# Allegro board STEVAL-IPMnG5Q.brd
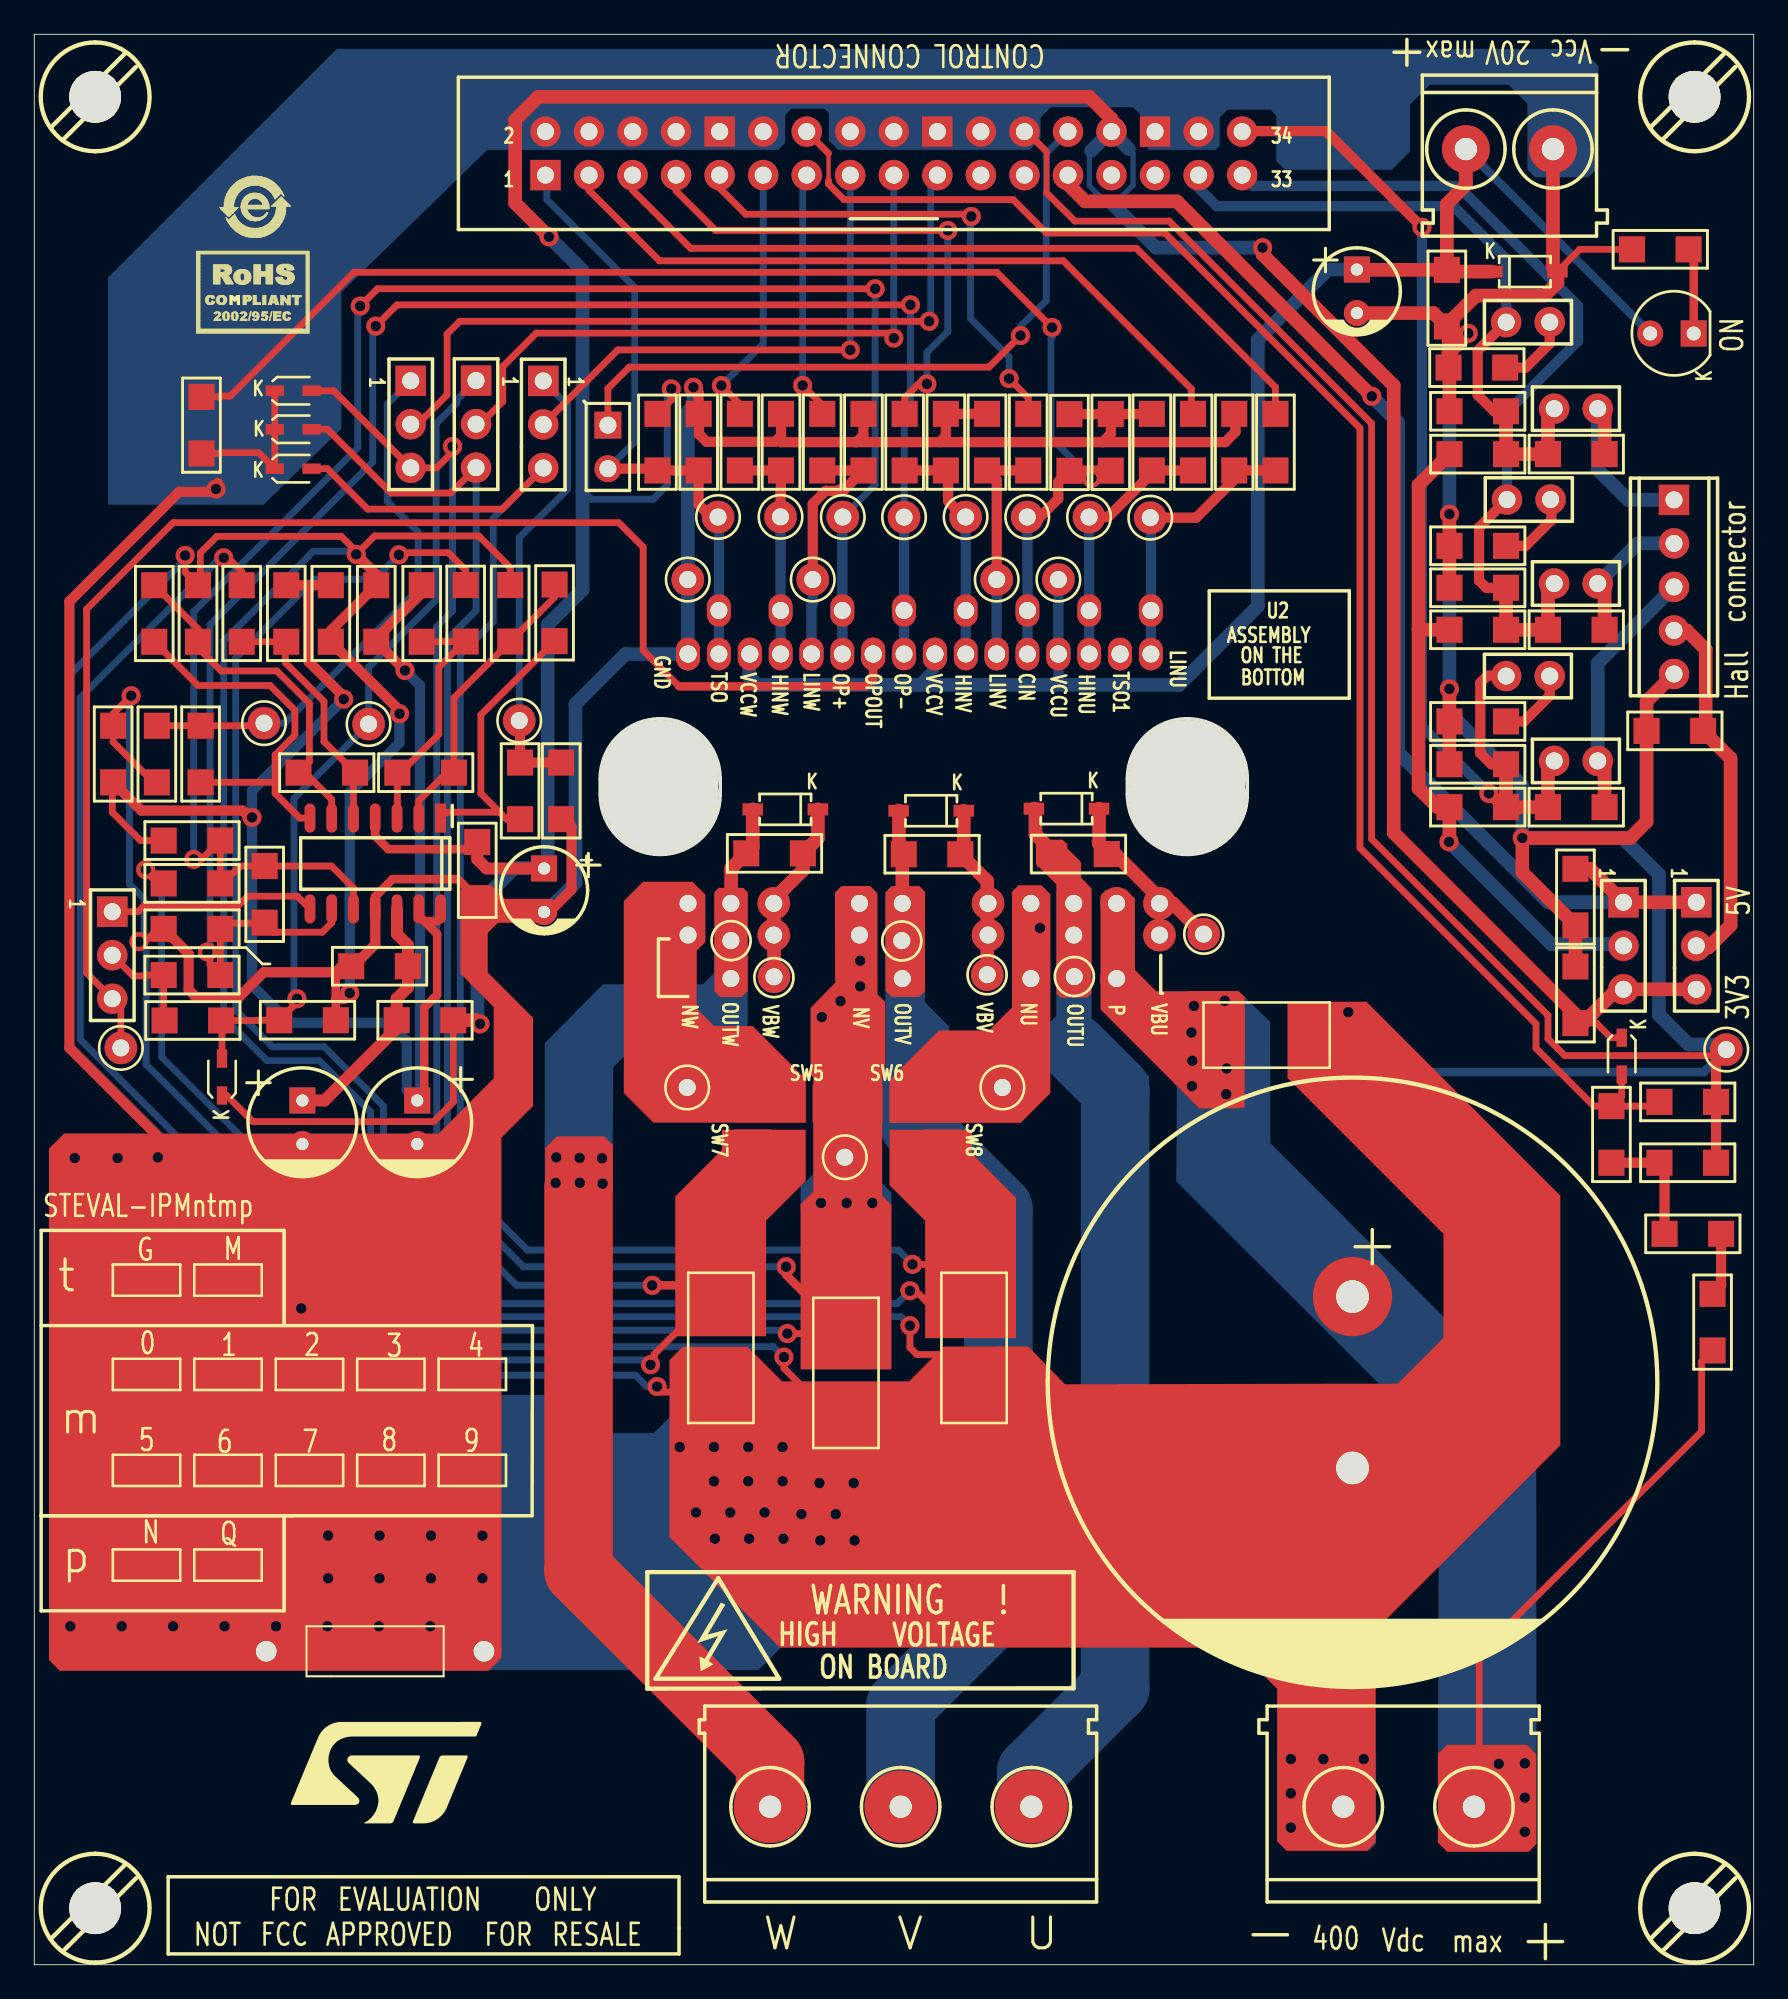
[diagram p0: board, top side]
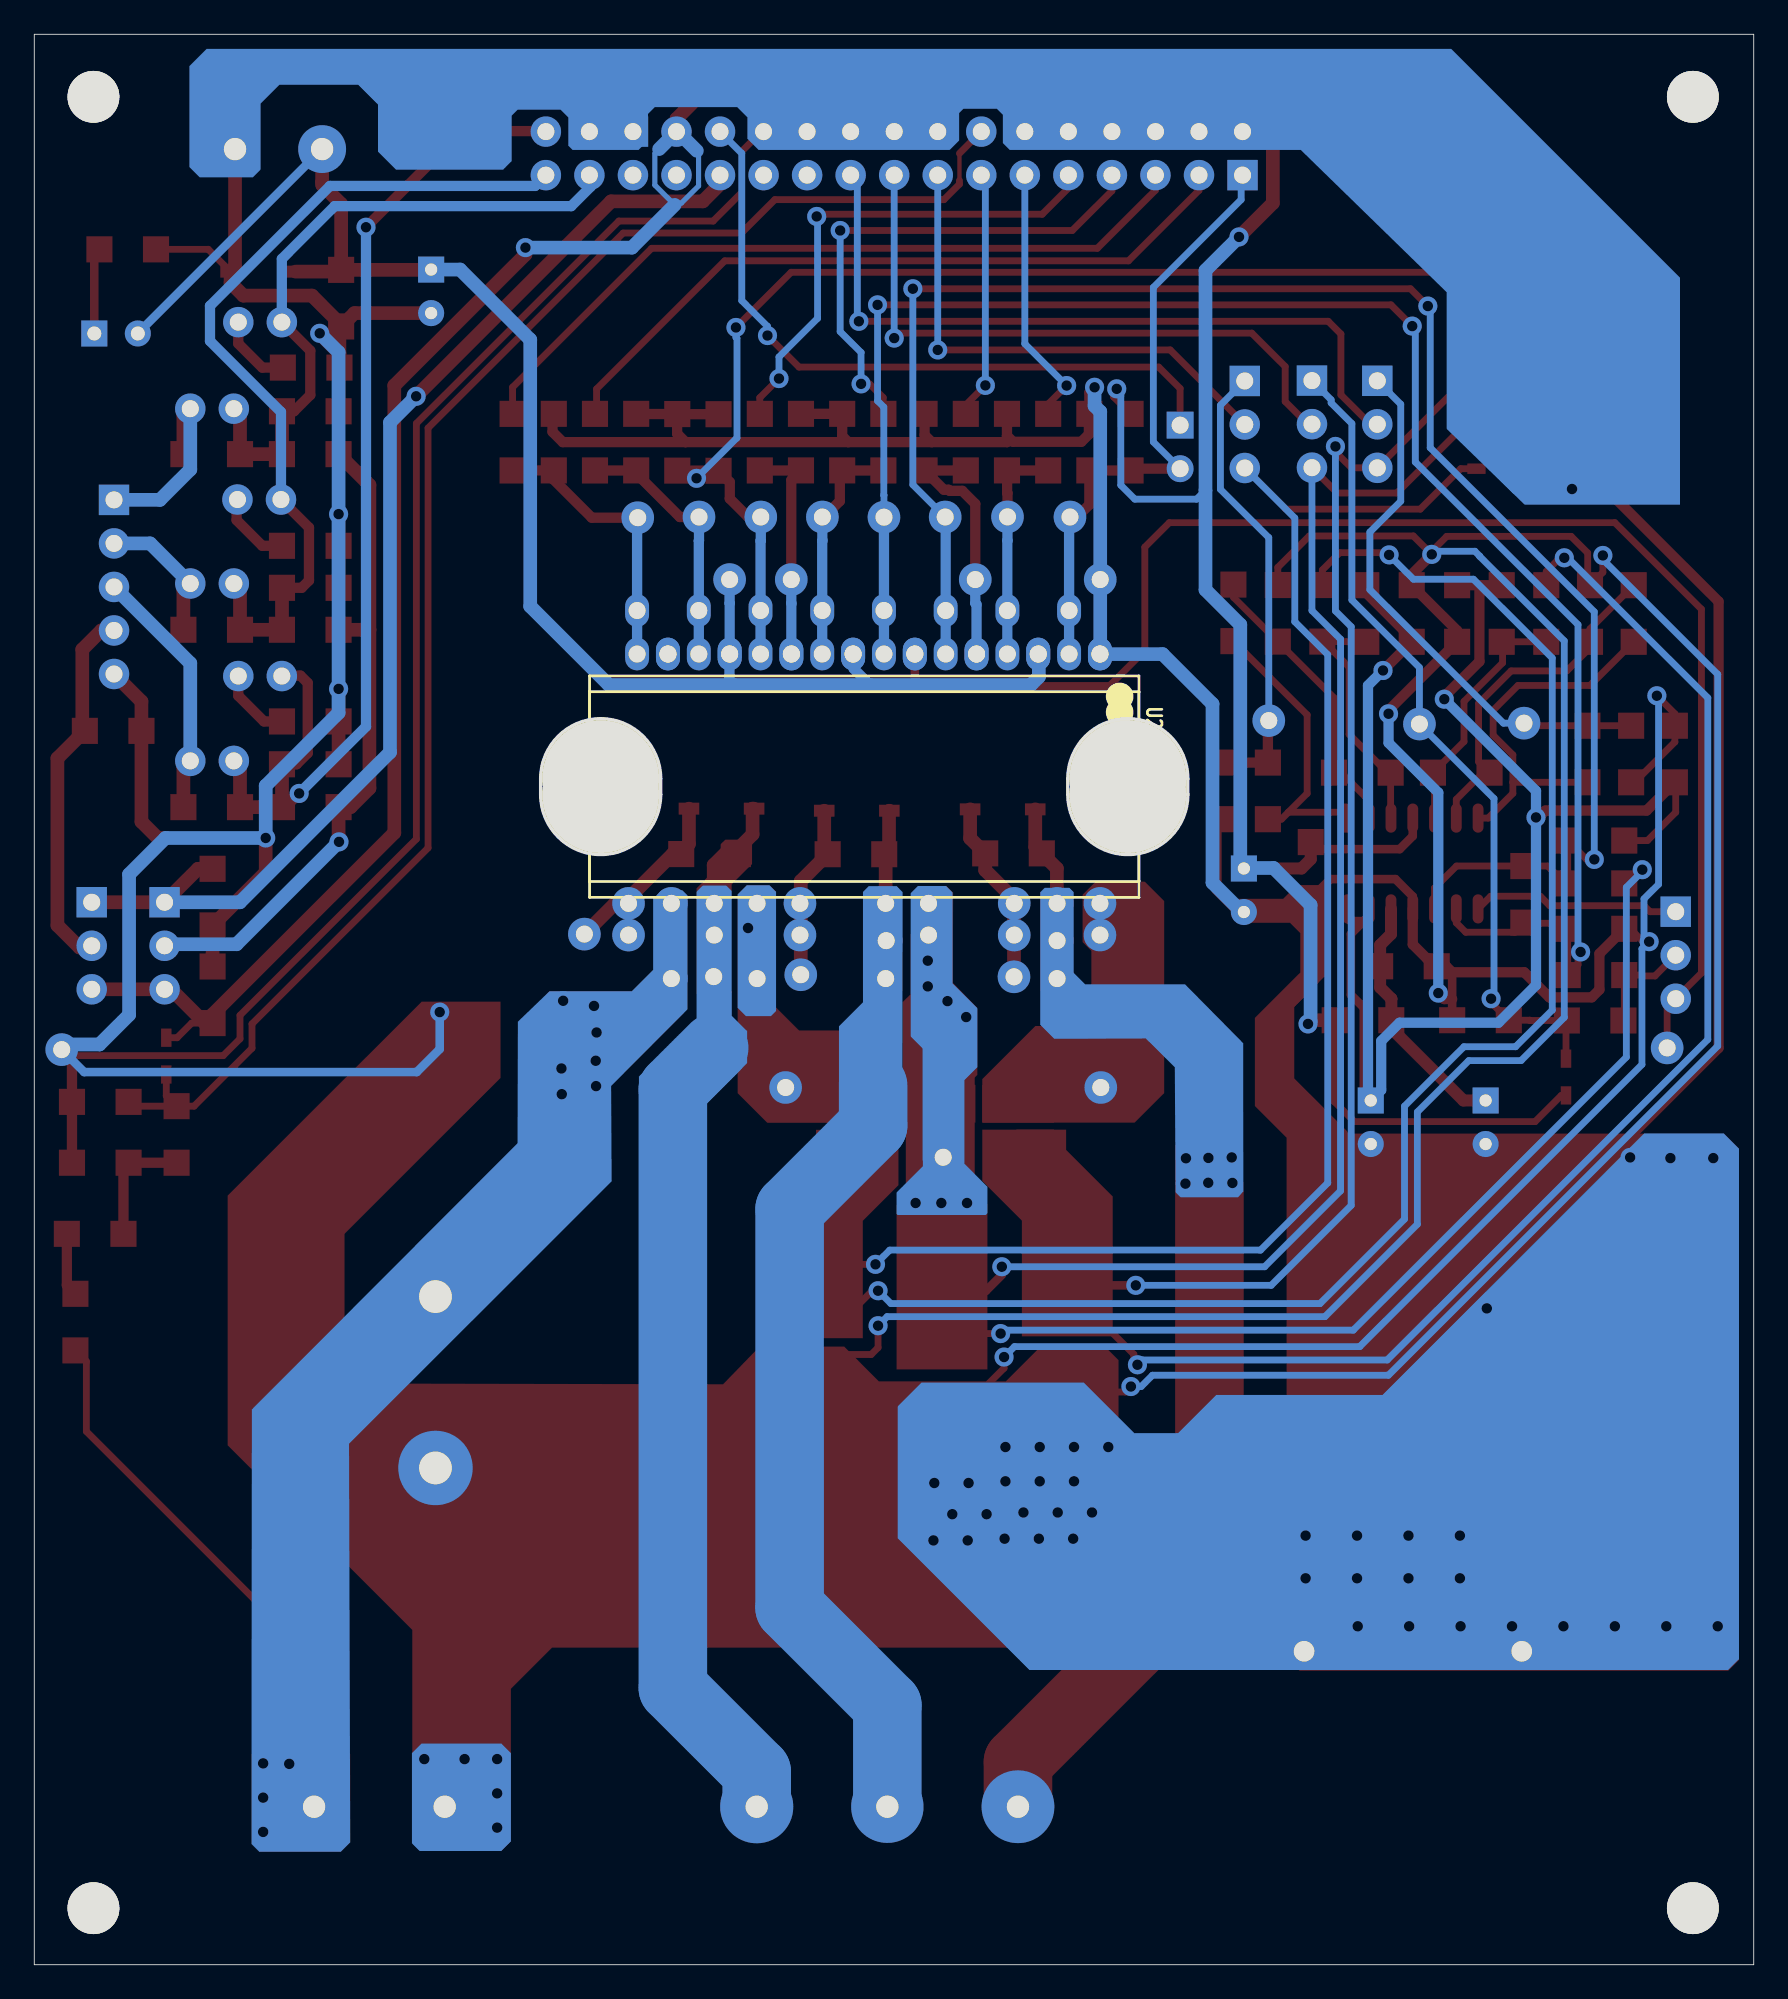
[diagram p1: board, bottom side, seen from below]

Outline 100.3 x 112.65 mm; copper layers: TOP, BOTTOM. Coordinates in mm from the lower left corner of the outline.
Outline path: 0,112.65 100.3,112.65 100.3,0 0,0 0,112.65 ; 33.01,69.21 arc(36.51,72.72) 40.01,69.21 40.01,68.28 arc(36.51,64.78) 33.01,68.28 33.01,69.21 ; 63.76,69.21 arc(67.26,72.72) 70.76,69.21 70.76,68.28 arc(67.26,64.78) 63.76,68.28 63.76,69.21

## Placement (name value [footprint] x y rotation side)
C1  330u/400V  [CPCYL_D1400_LS393_75D]  76.9 33.99 270 top
C2  10n  [SM_C_1206]  96.45 50.35 0 top
C3  47u/35V  [CPCYL_D250_LS100_28D]  15.64 49.16 270 top
C4  47u/35V  [CPCYL_D250_LS100_28D]  22.34 49.16 270 top
C5  2.2u  [SM_R_1206]  60.91 64.81 180 top
C6  2.2u  [SM_R_1206]  52.37 64.8 180 top
C7  2.2u  [SM_R_1206]  43.18 64.85 180 top
C8  1n  [SM_C_1206]  60.39 88.83 90 top
C10  10p  [SM_C_1206]  53.17 88.85 90 top
C11  10p  [SM_C_1206]  48.37 88.85 90 top
C12  10u 50V  [CPCYL_D200_LS100_28D]  77.15 97.65 270 top
C13  100n  [SM_C_1206]  82.4 97.25 90 top
C14  10p  [SM_C_1206]  55.58 88.85 90 top
C15  10p  [SM_C_1206]  70 88.85 90 top
C16  10p  [SM_C_1206]  65.19 88.85 90 top
C17  0,1 uF - 400V  [SMC1812]  69.6 54.25 0 top
C18  3.3n  [SM_C_1206]  38.75 88.85 90 top
C19  10p  [SM_C_1206]  43.56 88.85 90 top
C21  4.7u 50V  [CPCYL_D200_LS100_28D]  29.74 62.7 270 top
C22  10n  [SM_C_1206]  19.95 78.85 90 top
C23  100n  [SM_C_1206]  25.84 63.86 270 top
C24  100p  [SM_C_1206]  22.83 69.56 0 top
C25  330p  [SM_C_1206]  30.74 68.5 270 top
C26  10n  [SM_C_1206]  4.6 70.65 90 top
C27  100p  [SM_C_1206]  13.44 62.46 270 top
C28  10n  [SM_C_1206]  17.3 78.85 270 top
C29  330p  [SM_C_1206]  15.94 55.12 0 top
C30  100p  [SM_C_1206]  17.06 69.56 180 top
C31  330p  [SM_C_1206]  7.15 70.65 270 top
C32  100n  [SM_C_1206]  89.9 56.6 90 top
C33  100n  [SM_C_1206]  89.9 62.3 270 top
C34  100n  [SM_C_1206]  95.7 72 180 top
C35  10p  [SM_C_1206]  84.2 90.65 180 top
C36  10p  [SM_C_1206]  84.2 80.35 180 top
C37  10p  [SM_C_1206]  84.2 70.05 180 top
D1  BAT48JFILM  [SM_SOD-323]  92.6 53.02 270 top
D2  LED Red  [LED3MM]  95.53 95.19 0 top
D3  BAT48JFILM  [SM_SOD-323]  15.1 91.85 0 top
D4  BAT48JFILM  [SM_SOD-323]  15.1 89.6 0 top
D5  BAT48JFILM  [SM_SOD-323]  15.1 87.3 0 top
D6  MMSZ5250B  [SOD123]  43.81 67.42 0 top
D7  MMSZ5250B  [SOD123]  52.32 67.34 0 top
D8  MMSZ5250B  [SOD123]  60.21 67.46 0 top
D9  MMSZ5250B  [SOD123]  86.95 98.8 180 top
D10  BAT48JFILM  [SM_SOD-323]  10.95 51.8 90 top
J1  INPUT-dc  [MOR2_7_62MM]  83.98 9.22 90 top
J2  Control Connector  [CONN_IDC_34_HEADER]  50.14 105.7 0 top
J3  Motor Output  [MOR3_7_62MM]  50.54 9.22 90 top
J4  15V  [MOR2_5_08MM]  86.05 105.95 270 top
J5  Encoder/Hall  [STRIP5_SHROUDED_HEADERS_100M_V]  95.65 80.4 270 top
NOREF  -  []  61.99 87.24 90 top
NOREF#2  -  []  7.55 33.83 90 top
NOREF#3  -  []  52.02 50.13 0 top
NOREF#4  -  []  16 91.12 90 top
NOREF#5  -  []  26.55 33.83 90 top
NOREF#6  -  []  5.55 35.08 0 top
NOREF#7  -  []  21.23 68.76 0 top
NOREF#8  -  []  53.74 24.05 0 top
NOREF#9  -  []  25.04 62.26 90 top
NOREF#10  -  []  79.4 77.1 0 top
NOREF#11  -  []  10.3 35.08 0 top
NOREF#12  -  []  45.31 66.52 90 top
NOREF#13  -  []  23.3 28.23 90 top
NOREF#14  -  []  44.36 87.25 90 top
NOREF#15  -  []  63.14 57.55 90 top
NOREF#16  -  []  82.6 71.75 90 top
NOREF#17  -  []  42.76 90.45 0 top
NOREF#18  -  []  14.4 27.25 0 top
NOREF#19  -  []  35.86 65.89 0 top
NOREF#20  -  []  12.3 28.23 90 top
NOREF#21  -  []  20.75 77.25 90 top
NOREF#22  -  []  49.17 87.25 90 top
NOREF#23  -  []  19.15 80.45 0 top
NOREF#24  -  []  4.9 32.85 0 top
NOREF#25  -  []  82.6 82 90 top
NOREF#26  -  []  36.51 69.21 0 top
NOREF#27  -  []  17.54 54.32 90 top
NOREF#28  -  []  15.46 68.76 90 top
NOREF#29  -  [unnamed#2]  96.85 109 0 top
NOREF#30  -  []  27.1 30.45 0 top
NOREF#31  -  []  35.55 87.25 0 top
NOREF#32  -  []  44.01 51.16 0 top
NOREF#33  -  []  57.18 87.25 0 top
NOREF#34  -  []  5.4 69.05 90 top
NOREF#35  -  []  29.94 66.9 0 top
NOREF#36  -  []  13 102.53 0 top
NOREF#37  -  []  83.51 105.95 0 top
NOREF#38  -  []  8.95 88.24 90 top
NOREF#39  -  []  66.79 87.25 90 top
NOREF#40  -  []  7.6 62.3 0 top
NOREF#41  -  [unnamed#2]  3.55 109 0 top
NOREF#42  -  []  94.1 72.8 0 top
NOREF#43  -  []  50.42 67.34 0 top
NOREF#44  -  []  17.05 33.83 90 top
NOREF#45  -  []  97.1 39.1 0 top
NOREF#46  -  []  7.6 58.55 0 top
NOREF#47  -  []  12.62 97.08 0 top
NOREF#48  -  []  54.78 90.45 0 top
NOREF#49  -  []  64.39 90.45 0 top
NOREF#50  -  []  10.8 59.65 90 top
NOREF#51  -  []  38.14 60.09 0 top
NOREF#52  -  []  91.55 88.95 0 top
NOREF#53  -  []  27.54 66.9 0 top
NOREF#54  -  []  98.05 46 90 top
NOREF#55  -  []  91.55 68.35 0 top
NOREF#56  -  []  18.55 30.23 0 top
NOREF#57  -  []  71.6 87.25 90 top
NOREF#58  -  []  0 112.65 0 top
NOREF#59  -  []  82.6 89.85 90 top
NOREF#60  -  []  44.08 50.99 0 top
NOREF#61  -  []  70.8 87.25 90 top
NOREF#62  -  []  16 86.58 90 top
NOREF#63  -  []  91.88 52.12 90 top
NOREF#64  -  []  6.2 77.25 90 top
NOREF#65  -  []  26.96 77.26 90 top
NOREF#66  -  []  33.46 87.3 90 top
NOREF#67  -  []  56.38 87.25 90 top
NOREF#68  -  []  41.16 47.45 0 top
NOREF#69  -  []  29.94 66.9 90 top
NOREF#70  -  []  8.1 24.92 0 top
NOREF#71  -  []  24.55 35.08 0 top
NOREF#72  -  []  52.55 47.45 90 top
NOREF#73  -  []  21.74 57.47 90 top
NOREF#74  -  []  27.54 66.9 90 top
NOREF#75  -  []  98.05 49.55 90 top
NOREF#76  -  []  79.4 65.15 90 top
NOREF#77  -  []  11.3 77.25 0 top
NOREF#78  -  []  5.55 29.48 0 top
NOREF#79  -  []  13.21 51.2 0 top
NOREF#80  -  []  48.2 50.99 0 top
NOREF#81  -  []  14.34 54.32 0 top
NOREF#82  -  []  6.35 69.05 90 top
NOREF#83  -  []  94.85 49.55 0 top
NOREF#84  -  []  32.25 63.09 0 top
NOREF#85  -  []  22.35 30.45 0 top
NOREF#86  -  []  49.97 87.25 90 top
NOREF#87  -  []  93.25 100.9 0 top
NOREF#88  -  []  65.99 87.25 90 top
NOREF#89  -  []  85.05 98.8 0 top
NOREF#90  -  []  14.2 86.58 0 top
NOREF#91  -  []  22.43 66.91 0 top
NOREF#92  -  []  69.2 90.45 0 top
NOREF#93  -  []  4.9 38.35 0 top
NOREF#94  -  []  9.65 32.85 0 top
NOREF#95  -  []  36.51 68.28 0 top
NOREF#96  -  []  10.23 52.7 0 top
NOREF#97  -  []  8.9 69.05 90 top
NOREF#98  -  []  25.04 62.26 0 top
NOREF#99  -  []  85.45 97.9 90 top
NOREF#100  -  []  66.79 87.25 0 top
NOREF#101  -  []  38.14 61.94 0 top
NOREF#102  -  []  19.15 32.85 0 top
NOREF#103  -  []  100.3 0 90 top
NOREF#104  -  []  79.66 98.04 0 top
NOREF#105  -  []  7.65 54.3 90 top
NOREF#106  -  []  93.25 99.3 90 top
NOREF#107  -  []  91.55 78.7 0 top
NOREF#108  -  []  59.31 65.61 0 top
NOREF#109  -  []  58.31 67.46 0 top
NOREF#110  -  []  21.8 33.83 90 top
NOREF#111  -  []  50.77 64 90 top
NOREF#112  -  []  41.58 64.05 90 top
NOREF#113  -  []  8.95 88.24 0 top
NOREF#114  -  []  12.85 24.92 0 top
NOREF#115  -  []  94.1 71.2 90 top
NOREF#116  -  []  59.31 64.01 90 top
NOREF#117  -  []  7.6 64.8 90 top
NOREF#118  -  []  29.55 77.29 0 top
NOREF#119  -  []  15.64 47.89 90 top
NOREF#120  -  []  5.55 40.58 0 top
NOREF#121  -  []  11.3 77.25 90 top
NOREF#122  -  []  24.74 101.25 90 top
NOREF#123  -  []  7.65 55.9 0 top
NOREF#124  -  []  40.36 87.25 0 top
NOREF#125  -  []  15.5 77.25 90 top
NOREF#126  -  []  82.6 91.45 0 top
NOREF#127  -  []  57.18 87.25 90 top
NOREF#128  -  []  29.82 104.43 0 top
NOREF#129  -  []  24.36 77.26 90 top
NOREF#130  -  []  92.8 46.85 90 top
NOREF#131  -  []  59.59 90.43 0 top
NOREF#132  -  []  79.4 87.35 0 top
NOREF#133  -  []  82.6 83.6 0 top
NOREF#134  -  []  14.2 91.12 0 top
NOREF#135  -  []  4.3 24.7 0 top
NOREF#136  -  []  8.9 69.05 0 top
NOREF#137  -  []  95.15 43.45 0 top
NOREF#138  -  [unnamed#2]  3.55 3.3 0 top
NOREF#139  -  []  24.43 68.76 90 top
NOREF#140  -  []  7.6 59.65 0 top
NOREF#141  -  []  42.75 87.25 90 top
NOREF#142  -  []  94.26 95.19 0 top
NOREF#143  -  []  81.6 98.85 0 top
NOREF#144  -  []  45.16 87.25 0 top
NOREF#145  -  []  95.15 41.85 90 top
NOREF#146  -  []  23.4 77.25 90 top
NOREF#147  -  []  83.2 95.65 90 top
NOREF#148  -  []  9.65 27.25 0 top
NOREF#149  -  []  21.19 54.32 0 top
NOREF#150  -  []  82.6 79.55 90 top
NOREF#151  -  []  19.91 51.2 0 top
NOREF#152  -  []  85.9 63.9 0 top
NOREF#153  -  []  22.34 47.89 90 top
NOREF#154  -  []  41.58 65.65 0 top
NOREF#155  -  []  61.71 66.56 90 top
NOREF#156  -  []  77.15 96.38 90 top
NOREF#157  -  [unnamed#2]  96.85 3.3 0 top
NOREF#158  -  []  49.97 87.25 0 top
NOREF#159  -  []  12.3 33.83 90 top
NOREF#160  -  []  82.55 94 0 top
NOREF#161  -  []  71.6 87.25 0 top
NOREF#162  -  []  29.74 61.43 90 top
NOREF#163  -  []  39.55 87.25 0 top
NOREF#164  -  []  4.3 22.7 90 top
NOREF#165  -  []  23.9 32.85 0 top
NOREF#166  -  []  79.4 75.5 90 top
NOREF#167  -  []  41.91 67.42 0 top
NOREF#168  -  []  6.2 77.25 0 top
NOREF#169  -  []  61.19 87.23 90 top
NOREF#170  -  []  15.05 35.08 0 top
NOREF#171  -  []  87.5 53.4 90 top
NOREF#172  -  []  9.05 22.7 90 top
NOREF#173  -  []  79.4 85.75 90 top
NOREF#174  -  []  85.9 62.3 90 top
NOREF#175  -  []  40.36 87.25 90 top
NOREF#176  -  []  14.4 32.85 0 top
NOREF#177  -  []  94.75 68.35 90 top
NOREF#178  -  []  79.4 66.75 0 top
NOREF#179  -  []  19.8 35.08 0 top
NOREF#180  -  []  13.3 5.1 0 top
NOREF#181  -  []  15.54 62.26 0 top
NOREF#182  -  []  23.3 30.23 0 top
NOREF#183  -  []  10.3 40.58 0 top
NOREF#184  -  []  40.95 50.13 0 top
NOREF#185  -  []  9.65 38.35 0 top
NOREF#186  -  []  26.96 77.26 0 top
NOREF#187  -  []  61.99 87.24 0 top
NOREF#188  -  []  47.57 90.45 0 top
NOREF#189  -  []  25.05 60.76 90 top
NOREF#190  -  []  21.8 80.45 0 top
NOREF#191  -  []  98.7 35.9 90 top
NOREF#192  -  []  24.74 110.15 0 top
NOREF#193  -  []  53.82 66.44 90 top
NOREF#194  -  []  29.55 77.29 90 top
NOREF#195  -  []  53.97 87.25 90 top
NOREF#196  -  []  65.64 61.94 90 top
NOREF#197  -  []  7.55 39.33 90 top
NOREF#198  -  []  16 88.88 90 top
NOREF#199  -  []  15.05 29.48 0 top
NOREF#200  -  []  70.46 104.43 90 top
NOREF#201  -  []  12.64 60.86 90 top
NOREF#202  -  []  91.88 52.12 0 top
NOREF#203  -  []  87.5 55 0 top
NOREF#204  -  []  3.8 72.25 0 top
NOREF#205  -  []  18.55 28.23 90 top
NOREF#206  -  []  82.6 70.85 0 top
NOREF#207  -  []  50.77 65.6 0 top
NOREF#208  -  []  35.55 87.25 90 top
NOREF#209  -  []  12.64 60.86 0 top
NOREF#210  -  []  94.75 88.95 90 top
NOREF#211  -  []  7.55 28.23 90 top
NOREF#212  -  []  7.6 56.95 90 top
NOREF#213  -  []  91.2 50.05 0 top
NOREF#214  -  []  15.46 70.36 0 top
NOREF#215  -  []  16.5 77.25 90 top
NOREF#216  -  []  24.36 77.26 0 top
NOREF#217  -  []  44.08 49.95 90 top
NOREF#218  -  []  6.35 69.05 0 top
NOREF#219  -  []  18.54 57.47 0 top
NOREF#220  -  []  14.2 88.88 0 top
NOREF#221  -  []  52.55 47.45 0 top
NOREF#222  -  []  48.2 49.9 90 top
NOREF#223  -  []  45.16 87.25 90 top
NOREF#224  -  []  4.9 27.25 0 top
NOREF#225  -  []  8.75 77.25 90 top
NOREF#226  -  []  7.6 66.4 0 top
NOREF#227  -  []  12.3 39.33 90 top
NOREF#228  -  []  52.37 90.45 0 top
NOREF#229  -  []  82.55 92.4 90 top
NOREF#230  -  []  10.3 29.48 0 top
NOREF#231  -  []  10.8 62.3 90 top
NOREF#232  -  []  38.14 76.48 0 top
NOREF#233  -  []  48.5 51.16 0 top
NOREF#234  -  []  94.85 46 0 top
NOREF#235  -  []  13.9 80.45 0 top
NOREF#236  -  []  9.05 24.7 0 top
NOREF#237  -  []  82.6 69.25 90 top
NOREF#238  -  []  16.5 77.25 0 top
NOREF#239  -  []  82.6 73.35 0 top
NOREF#240  -  []  94.75 78.7 90 top
NOREF#241  -  []  8.75 77.25 0 top
NOREF#242  -  []  65.64 60.09 90 top
NOREF#243  -  []  17.05 28.23 90 top
NOREF#244  -  []  11.67 50.9 90 top
NOREF#245  -  []  24.39 54.32 90 top
NOREF#246  -  []  35.86 66.81 0 top
NOREF#247  -  []  41.16 47.45 90 top
NOREF#248  -  []  82.6 81.15 0 top
NOREF#249  -  [unnamed#3]  51.89 68.28 0 bottom
R1  470K  [SM_R_1206]  97.9 37.5 90 top
R2  470K  [SM_R_1206]  96.75 42.65 180 top
R3  120R  [SM_R_1206]  92 48.45 90 top
R4  7k5  [SM_R_1206]  96.45 46.8 0 top
R5  1k0  [SM_R_1206]  22.79 55.12 0 top
R6  1k0  [SM_R_1206]  20.14 58.27 0 top
R7  1k0  [SM_R_1206]  41.16 88.85 270 top
R8  1k0  [SM_R_1206]  50.77 88.85 270 top
R9  1k0  [SM_R_1206]  45.96 88.85 270 top
R10  1k0  [SM_R_1206]  36.35 88.85 270 top
R11  4k7  [SM_R_1206]  62.79 88.84 270 top
R12  5k6  [SM_R_1206]  94.85 100.1 180 top
R13  1k0  [SM_R_1206]  72.4 88.85 270 top
R14  1k0  [SM_R_1206]  57.98 88.85 270 top
R15  1k0  [SM_R_1206]  9.75 89.84 270 top
R16  0.2 1W  [SMR2512]  40.05 38.99 270 top
R17  0.2 1W  [SMR2512]  47.35 37.53 270 top
R18  0.2 1W  [SMR2512]  54.82 38.99 270 top
R19  1k0  [SM_R_1206]  67.59 88.85 270 top
R20  1k9  [SM_R_1206]  22.6 78.85 90 top
R21  1k0  [SM_R_1206]  25.16 78.86 270 top
R22  1k  [SM_R_1206]  28.34 68.5 270 top
R23  1k0  [SM_R_1206]  27.76 78.86 270 top
R24  1k9  [SM_R_1206]  30.35 78.89 270 top
R25  1k9  [SM_R_1206]  9.2 65.6 180 top
R26  1k0  [SM_R_1206]  9.2 63.1 0 top
R27  1k0  [SM_R_1206]  9.2 60.45 0 top
R28  1k9  [SM_R_1206]  14.7 78.85 90 top
R29  1k9  [SM_R_1206]  9.2 57.75 180 top
R30  1k0  [SM_R_1206]  12.1 78.85 270 top
R31  1k  [SM_R_1206]  9.7 70.65 270 top
R32  1k0  [SM_R_1206]  9.55 78.85 270 top
R33  1k9  [SM_R_1206]  7 78.85 270 top
R34  4k7  [SM_R_1206]  84.2 88.15 0 top
R35  4k7  [SM_R_1206]  84.2 77.9 0 top
R36  4k7  [SM_R_1206]  84.2 67.55 0 top
R37  2k4  [SM_R_1206]  89.95 88.15 180 top
R38  2k4  [SM_R_1206]  89.95 77.9 180 top
R39  2k4  [SM_R_1206]  89.95 67.55 180 top
R40  4k7  [SM_R_1206]  84.15 93.2 180 top
R41  4k7  [SM_R_1206]  84.2 82.8 180 top
R42  4k7  [SM_R_1206]  84.2 72.55 180 top
R43  1k  [SM_R_1206]  9.25 55.1 180 top
RC1  0  [SM_R_0805]  6.55 39.95 0 top
RC2  0  [SM_R_0805]  11.3 39.95 0 top
RC3  0  [SM_R_0805]  6.55 34.45 0 top
RC4  0  [SM_R_0805]  11.3 34.45 0 top
RC5  0  [SM_R_0805]  16.05 34.45 0 top
RC6  0  [SM_R_0805]  20.8 34.45 0 top
RC7  0  [SM_R_0805]  25.55 34.45 0 top
RC8  0  [SM_R_0805]  6.55 28.85 0 top
RC9  0  [SM_R_0805]  11.3 28.85 0 top
RC10  0  [SM_R_0805]  16.05 28.85 0 top
RC11  0  [SM_R_0805]  20.8 28.85 0 top
RC12  0  [SM_R_0805]  25.55 28.85 0 top
RC13  0  [SM_R_0805]  6.55 23.32 0 top
RC14  0  [SM_R_0805]  11.3 23.32 0 top
SW1  jump3  [STRIP3_100M_V]  29.69 92.42 270 top
SW2  jump3  [STRIP3_100M_V]  25.77 92.44 270 top
SW3  jump3  [STRIP3_100M_V]  21.96 92.43 270 top
SW4  SW SLIDE-SPST_0  [SIPTM2002]  33.46 89.84 270 top
SW5  SW SLIDE-SPST_0  [SM_R_0603]  45.2 50.24 0 top
SW6  SW SLIDE-SPST_0  [SM_R_0603]  49.69 50.24 0 top
SW7  SW SLIDE-SPST_0  [SM_R_0603]  41.91 48.94 90 top
SW8  SW SLIDE-SPST_0  [SM_R_0603]  52.98 48.94 90 top
SW9  jump3  [STRIP3_100M_V]  92.7 62 270 top
SW10  SW SLIDE-SPST_0  [JUMPER100M]  91.2 90.8 180 top
SW11  SW SLIDE-SPST_0  [JUMPER100M]  91.2 80.6 180 top
SW12  SW SLIDE-SPST_0  [JUMPER100M]  91.2 70.25 180 top
SW13  SW SLIDE-SPST_0  [JUMPER100M]  88.4 95.85 180 top
SW14  SW SLIDE-SPST_0  [JUMPER100M]  88.45 85.5 180 top
SW15  SW SLIDE-SPST_0  [JUMPER100M]  88.4 75.2 180 top
SW16  jump3  [STRIP3_100M_V]  96.95 62 270 top
SW17  jump3  [STRIP3_100M_V]  4.55 61.45 270 top
TP1  T POINT F  [TESTPOINT_1MM]  40.64 59.76 0 top
TP2  T POINT F  [TESTPOINT_1MM]  43.53 84.49 0 top
TP3  T POINT F  [TESTPOINT_1MM]  59.74 80.83 0 top
TP4  T POINT F  [TESTPOINT_1MM]  39.89 84.48 0 top
TP5  T POINT F  [TESTPOINT_1MM]  45.41 80.83 0 top
TP6  T POINT F  [TESTPOINT_1MM]  47.16 84.48 0 top
TP7  T POINT F  [TESTPOINT_1MM]  5.05 53.5 0 top
TP8  T POINT F  [TESTPOINT_1MM]  50.74 84.47 0 top
TP9  T POINT F  [TESTPOINT_1MM]  43.15 57.65 0 top
TP10  T POINT F  [TESTPOINT_1MM]  50.61 59.76 0 top
TP11  T POINT F  [TESTPOINT_1MM]  47.28 47.12 0 top
TP12  T POINT F  [TESTPOINT_1MM]  54.33 84.48 0 top
TP13  T POINT F  [TESTPOINT_1MM]  55.59 57.77 0 top
TP14  T POINT F  [TESTPOINT_1MM]  56.14 80.83 0 top
TP15  T POINT F  [TESTPOINT_1MM]  57.92 84.48 0 top
TP16  T POINT F  [TESTPOINT_1MM]  56.47 51.19 0 top
TP17  T POINT F  [TESTPOINT_1MM]  38.09 51.19 0 top
TP18  T POINT F  [TESTPOINT_1MM]  60.67 57.66 0 top
TP19  T POINT F  [TESTPOINT_1MM]  68.21 60.14 0 top
TP20  T POINT F  [TESTPOINT_1MM]  65.1 84.44 0 top
TP21  SW SLIDE-SPST_0  [JUMP1M5PITCH12X7]  19.88 18.29 0 top
TP22  T POINT F  [TESTPOINT_1MM]  38.12 80.83 0 top
TP23  T POINT F  [TESTPOINT_1MM]  61.53 84.48 0 top
TP24  T POINT F  [TESTPOINT_1MM]  28.29 72.6 0 top
TP25  T POINT F  [TESTPOINT_1MM]  19.5 72.4 0 top
TP26  T POINT F  [TESTPOINT_1MM]  13.4 72.45 0 top
TP27  T POINT F  [TESTPOINT_1MM]  98.7 53.4 0 top
U1  TSV994  [SO14]  19.89 64.26 180 top
U2  STGIPQ5C60T-xy  [N2DIP26L]  51.89 69.21 0 bottom

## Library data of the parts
C1 = CAPACITOR POL_2
C2 C8 C10 C11 C13-C16 C18 C19 C22-C37 = CAPACITOR NON-POL
C3 C4 C12 C21 = CAPACITOR POL_1
C5-C7 C17 = C_0
D1 D10 = 1N4148_0
D2 = F5F1_1
D3 = DIODE_1
D4 = DIODE_2
D5 = DIODE_3
D6 = MA745/TO_0
D7 = MA745/TO_1
D8 = MA745/TO_2
D9 = MA745/TO_3
J1 J4 = CON2_0
J2 = CON34A
J3 = CON2_1
J5 = CON2_2
R1-R33 R37-R39 R43 RC1-RC14 = R_0
R34-R36 R40-R42 = R_1
SW1-SW3 SW9 SW16 SW17 = jump3
SW4-SW8 SW10-SW15 = SW SLIDE-SPST_0
TP1-TP20 TP22-TP27 = T POINT F
TP21 = SW SLIDE-SPST_4
U1 = TL084
U2 = 80C552/FP_19

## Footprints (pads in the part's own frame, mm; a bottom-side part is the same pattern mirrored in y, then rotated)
CONN_IDC_34_HEADER
  rect 1.778x1.778 hole 0.991: 1(-20.32,-1.27) 10(-10.16,1.27) 20(2.54,1.27) 30(15.24,1.27)
  round 1.778 hole 0.991: 2(-20.32,1.27) 3(-17.78,-1.27) 4(-17.78,1.27) 5(-15.24,-1.27) 6(-15.24,1.27) 7(-12.7,-1.27) 8(-12.7,1.27) 9(-10.16,-1.27) 11(-7.62,-1.27) 12(-7.62,1.27) 13(-5.08,-1.27) 14(-5.08,1.27) 15(-2.54,-1.27) 16(-2.54,1.27) 17(0,-1.27) 18(0,1.27) 19(2.54,-1.27) 21(5.08,-1.27) 22(5.08,1.27) 23(7.62,-1.27) 24(7.62,1.27) 25(10.16,-1.27) 26(10.16,1.27) 27(12.7,-1.27) 28(12.7,1.27) 29(15.24,-1.27) 31(17.78,-1.27) 32(17.78,1.27) 33(20.32,-1.27) 34(20.32,1.27)
CPCYL_D200_LS100_28D
  rect 1.524x1.524 hole 0.711: 1(-1.27,0)
  round 1.524 hole 0.711: 2(1.27,0)
CPCYL_D250_LS100_28D
  rect 1.524x1.524 hole 0.711: 1(-1.27,0)
  round 1.524 hole 0.711: 2(1.27,0)
CPCYL_D1400_LS393_75D
  rect 2.921x2.921 hole 1.905: 1(-5,0)
  round 2.921 hole 1.905: 2(5,0)
JUMP1M5PITCH12X7
  round 2.032 hole 1.199: 1(-6.35,0) 2(6.35,0)
JUMPER100M
  round 1.778 hole 0.991: 1(0,0) 2(2.54,0)
LED3MM
  round 1.524 hole 0.813: 1(-1.27,0)
  rect 1.524x1.524 hole 0.813: 2(1.27,0)
MOR2_5_08MM
  round 2.794 hole 1.3: 1(0,2.54) 2(0,-2.54)
MOR2_7_62MM
  rect 2.794x2.794 hole 1.3: 1(0,0)
  round 2.794 hole 1.3: 2(0,7.62)
MOR3_7_62MM
  round 2.794 hole 1.3: 1(0,-7.62) 2(0,0) 3(0,7.62)
N2DIP26L
  round 6.8 hole 7 unplated: (-15.375,0) (15.375,0)
  oval 1.397x1.905 hole 0.991: 1(-13.75,-7.275) 2(-11.95,-7.275) 3(-10.15,-7.275) 4(-8.35,-7.275) 5(-6.55,-7.275) 6(-4.75,-7.275) 7(-2.95,-7.275) 8(-1.15,-7.275) 9(0.65,-7.275) 10(2.45,-7.275) 11(4.25,-7.275) 12(6.05,-7.275) 13(7.85,-7.275) 14(9.65,-7.275) 15(11.45,-7.275) 16(13.25,-7.275)
  round 1.905 hole 0.991: 17(13.75,7.275) 18(11.25,7.275) 19(8.75,7.275) 20(6.25,7.275) 21(3.75,7.275) 22(-1.25,7.275) 23(-3.75,7.275) 24(-8.75,7.275) 25(-11.25,7.275) 26(-13.75,7.275)
SIPTM2002
  rect 1.575x1.575 hole 0.991: 1(0,0)
  round 1.575 hole 0.991: 2(2.54,0)
SM_C_1206
  rect 1.524x1.524 smd: 1(-1.651,0) 2(1.651,0)
SM_R_0603
  rect 2x2.2 smd: 1(-1.2,0) 2(1.2,0)
SM_R_0805
  rect 1.194x1.194 smd: 1(1.053,0) 2(-1.053,0)
SM_R_1206
  rect 1.524x1.524 smd: 1(-1.651,0) 2(1.651,0)
SM_SOD-323
  rect 1.067x0.61 smd: 1(1.073,0) 2(-1.073,0)
SMC1812
  rect 2.032x3.048 smd: 1(0,0) 2(4.572,0)
SMR2512
  rect 1.93x3.048 smd: 1(0,0) 2(5.994,0)
SO14
  rect 0.635x1.702 smd: 1(-3.81,-2.649)
  oval 0.635x1.702 smd: 2(-2.54,-2.649) 3(-1.27,-2.649) 4(0,-2.649) 5(1.27,-2.649) 6(2.54,-2.649) 7(3.81,-2.649) 8(3.81,2.649) 9(2.54,2.649) 10(1.27,2.649) 11(0,2.649) 12(-1.27,2.649) 13(-2.54,2.649) 14(-3.81,2.649)
SOD123
  rect 1.2x0.7 smd: 1(-1.9,0) 2(1.9,0)
STRIP3_100M_V
  rect 1.778x1.778 hole 0.991: 1(0,0)
  round 1.778 hole 0.991: 2(2.54,0) 3(5.08,0)
STRIP5_SHROUDED_HEADERS_100M_V
  rect 1.778x1.778 hole 0.991: 1(-5.08,0)
  round 1.778 hole 0.991: 2(-2.54,0) 3(0,0) 4(2.54,0) 5(5.08,0)
TESTPOINT_1MM
  round 1.905 hole 0.991: 1(0,0)
unnamed#2
  round 3.023 hole 3.2 unplated: (0,0)
unnamed#3
  round 6.8 hole 7 unplated: (-15.375,0) (15.375,0)
  oval 1.397x1.905 hole 0.991: 1(-13.75,-8.2) 2(-11.95,-10.74) 3(-10.15,-8.2) 4(-8.35,-10.74) 5(-6.55,-8.2) 6(-4.75,-10.74) 7(-2.95,-8.2) 8(-1.15,-10.74) 9(0.65,-8.2) 10(2.45,-10.74) 11(4.25,-8.2) 12(6.05,-10.74) 13(7.85,-8.2) 14(9.65,-10.74) 15(11.45,-8.2) 16(13.25,-10.74)
  round 1.905 hole 0.991: 17(13.75,8.2) 18(11.25,10.74) 19(8.75,8.2) 20(6.25,10.74) 21(3.75,8.2) 22(-1.25,10.74) 23(-3.75,8.2) 24(-8.75,8.2) 25(-11.25,10.74) 26(-13.75,8.2)

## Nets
1.65V: C4.1(P) C22.1 C26.1 C28.1 R20.2 R25.2 R28.2 U1.13(IN-) U1.14(OUT)
3.3V: C21.1(P) C23.1 C32.1 D1.2(CATHODE) D10.2(CATHODE) J2.28 R5.2 R10.1 SW9.3 SW16.3 U1.4(V+)
+5V: C33.1 J2.25 SW9.1 SW16.1
GND_SIGNAL: C1.2(N) C2.2 C3.2(N) C4.2(N) C8.2 C10.2 C11.2 C12.2(N) C13.1 C14.2 C15.2 C16.2 C17.2 C18.2 C19.2 C21.2(N) C22.2 C23.2 C25.2 C26.2 C28.2 C29.2 C31.2 C32.2 C33.2 C34.2 C35.2 C36.2 C37.2 D9.1(ANODE) J1.2 J2.2 J2.4 J2.6 J2.8 J2.10 J2.12 J2.16 J2.18 J2.20 J2.22 J2.24 J2.30 J2.32 J4.1 J5.5 R4.2 R6.1 R11.1 R12.2 R16.2 R17.2 R18.2 R23.1 R27.1 R32.1 R40.2 R41.2 R42.2 RC1.1 RC1.2 RC2.1 RC2.2 RC3.1 RC3.2 RC4.1 RC4.2 RC5.1 RC5.2 RC6.1 RC6.2 RC7.1 RC7.2 RC8.1 RC8.2 RC9.1 RC9.2 RC10.1 RC10.2 RC11.1 RC11.2 RC12.1 RC12.2 RC13.1 RC13.2 RC14.1 RC14.2 TP21.1 TP21.2(NO) TP22.1(TP) TP27.1(TP) U1.11(V-) U2.1(GND)
+BUS: C1.1(P) C17.1 J1.1 R1.1 U2.18(P)
BUS_VOLTAGE: C2.1 D1.1(ANODE) J2.14 R3.2
CURRENT_A: J2.15 SW1.2
CURRENT_A_AMP: C25.1 R22.1 SW1.1 TP24.1(TP)
CURRENT_B: J2.17 SW2.2
CURRENT_B_AMP: C29.1 D10.1(ANODE) R43.1 SW2.1 TP25.1(TP)
CURRENT_C: J2.19 SW3.2
CURRENT_C_AMP: C31.1 R31.1 SW3.1 TP26.1(TP)
E1: D5.1(A) R18.1 R21.1 SW1.3 SW8.1
E2: D4.1(A) R17.1 R26.1 SW2.3 SW5.2(NO) SW6.1 TP11.1(TP) U2.23(NV)
E3: D3.1(A) R16.1 R30.1 SW3.3 SW7.1
EM_STOP: C18.1 J2.1 R10.2 SW4.2(NO) TP4.1(TP) U2.2(T/S\D\/OD)
M_PHASE_A: C35.1 J2.31 R34.2 R37.2 SW10.2(NO) SW13.2(NO)
M_PHASE_B: C36.1 J2.33 R35.2 R38.2 SW11.2(NO) SW14.2(NO)
M_PHASE_C: C37.1 J2.34 R36.2 R39.2 SW12.2(NO) SW15.2(NO)
NANO OP+: C27.1 R25.1 R26.2 TP6.1(TP) U1.10(IN+) U2.6(OP+)
NANO OP-: C27.2 R27.2 R29.1 TP8.1(TP) U1.9(IN-) U2.8(OP-)
NANO OPOUT: SW17.3 TP7.1(TP) U2.7(OPOUT)
NTC: J2.26 SW4.1
NTC_BYPASS_RELAY: J2.21
PHASE_A: C5.2 D8.1(ANODE) J3.1 TP18.1(TP) U2.19(U,OUTU)
PHASE_B: C6.2 D7.1(ANODE) J3.2 TP10.1(TP) U2.22(V,OUTV)
PHASE_C: C7.2 D6.1(ANODE) J3.3 TP1.1(TP) U2.25(W, OUTW)
PWM-A-H: J2.3 R19.1
PWM-A-L: J2.5 R13.1
PWM-B-H: J2.7 R8.1
PWM-B-L: J2.9 R14.1
PWM-C-H: J2.11 R7.1
PWM-C-L: J2.13 R9.1
PWM_VREF: J2.29
N6680355: R1.2 R2.1
N6680429: R2.2 R3.1 R4.1
N7418873: C19.1 R7.2 TP2.1(TP) U2.4(HINW)
N7419173: C11.1 R9.2 TP5.1(TP) U2.5(LINW)
N7419575: C15.1 R13.2 TP20.1(TP) U2.16(LINU)
N7419579: C16.1 R19.2 TP23.1(TP) U2.14(HINU)
N7419959: C14.1 R14.2 TP14.1(TP) U2.11(LINV)
N7419967: C10.1 R8.2 TP12.1(TP) U2.10(HINV)
N8602926: C24.1 R20.1 R21.2 U1.3(IN+)
N8603142: C24.2 R23.2 R24.1 U1.2(IN-)
N8608659: R22.2 R24.2 U1.1(OUT)
N8611164: C3.1(P) R5.1 R6.2 U1.12(IN+)
N8745560: D3.2(K) D4.2(K) D5.2(K) R15.2
N8758281: R29.2 R43.2 SW17.2
N8759020: R31.2 R33.2 U1.7(OUT)
N8759128: C30.1 R28.1 R30.2 U1.5(IN+)
N8759136: C30.2 R32.2 R33.1 U1.6(IN-)
N8769015: C34.1 J5.4 SW16.2
N8769177: R34.1 R35.1 R36.1 SW9.2
N8769259: J5.1 R37.1 SW10.1
N8769267: J5.2 R38.1 SW11.1
N8783110: J5.3 R39.1 SW12.1
N8796833: SW6.2(NO) SW8.2(NO) TP16.1(TP) U2.20(NU)
N8856248: C7.1 D6.2(CATHODE) TP9.1(TP) U2.24(VBOOTW)
N8857786: SW5.1 SW7.2(NO) TP17.1(TP) U2.26(NW)
N8867925: C8.1 R11.2 R15.1 TP15.1(TP) U2.12(CIN)
N8869100: C6.1 D7.2(CATHODE) TP13.1(TP) U2.21(VBOOTV)
N8869824: C5.1 D8.2(CATHODE) TP19.1(TP) U2.17(VBOOTU)
N8877212: C12.1(P) C13.2 D2.1(A) D9.2(CATHODE) J4.2 TP3.1(TP) U2.3(VCCW) U2.9(VCCV) U2.13(VCCU)
N8885403: SW17.1 U1.8(OUT)
N8906266: R42.1 SW15.1
N8906381: R41.1 SW14.1
N8906601: R40.1 SW13.1
N88772240: D2.2(C) R12.1

Pads without a net: J2 23 27; NOREF#249 1 2 3 4 5 6 7 8 9 10 11 12 13 14 15 16 17 18 19 20 21 22 23 24 25 26; U2 15

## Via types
v1: diameter 1.118, hole 0.61, TOP to BOTTOM, 125 vias

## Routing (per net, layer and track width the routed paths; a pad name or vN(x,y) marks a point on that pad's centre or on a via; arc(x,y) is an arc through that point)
1.65V: length 103.5
  TOP w0.4: C26.1 4.55,68.95 4.55,67.25 6.2,65.6 R25.2
  TOP w0.5: 22.75,60.9 23.5,60.15 23.5,56.6 22.75,55.85 22.75,50.84 C4.1 ; 22.75,60.9 23.52,60.9 23.7,61.08 U1.14 ; 22.75,60.9 22.43,61.22 U1.13
  TOP w0.6: v1(12.7,66.95) 12.55,66.95 12.15,67.35 6.25,67.35 C26.1 ; R28.2 16,80.5 ; 16,80.5 16,76.05 18.05,74 v1(18.05,73.85) ; 16,80.5 C28.1 ; R20.2 22.6,80.05 19.95,77.4 19.95,77.2 v1(21.62,75.52)
  BOTTOM w0.6: v1(21.62,75.52) 22.5,74.65 22.5,50.59 C4.1 21.73,51.04 21.73,53.9 20.66,54.97 14.89,54.97 12.7,57.16 v1(12.7,66.95) 12.7,68.5 v1(18.05,73.85)
3.3V: length 226.9
  TOP w0.4: D10.2 11.22,50.73 12.75,49.2 23.3,49.2 24.45,50.35 24.45,55.11 R5.2 ; D1.2 91.97,54.1 91.11,54.95 90.35,54.95 ; R10.1 37.34,91.49 37.34,91.96 v1(37.16,91.96)
  TOP w0.5: 25.84,65.51 25.43,65.1 20.65,65.1 19.89,65.86 U1.4
  TOP w0.7: C21.1 26.38,63.97 25.84,64.51 25.84,65.51
  TOP w0.8: v1(30.02,100.83) 28.05,102.8 28.05,107.65 29.4,109 61.55,109 62.84,107.71 62.84,106.97 ; R5.2 25.78,55.12 v1(26,54.9) ; SW16.3 SW9.3 92.6,56.82 92.22,56.82 90.35,54.95 C32.1 89.9,55.45 79.3,66.05 79.3,92.15 71.65,99.8 v1(71.65,100.2)
  BOTTOM w0.28: 64.1,105.7 63.85,105.95
  BOTTOM w0.3: 62.6,102.8 62.55,102.8 61.55,103.8 61.55,105.68 62.84,106.97
  BOTTOM w0.305: 62.94,102.69 64.1,103.85 64.1,105.7
  BOTTOM w0.4: v1(37.16,91.96) 37.33,91.96 36.92,91.55 36.92,86.34 36.1,85.52 32.5,85.52 31.98,86.04
  BOTTOM w0.8: 29.77,64 28,64 25.85,61.85 25.85,55.05 v1(26,54.9) ; 29.77,64 29.95,64.18 29.95,78.2 31.98,80.23 31.98,98.87 v1(30.02,100.83) ; 29.77,64 C21.1 ; 63.85,105.95 62.84,106.96 62.84,106.97 62.77,106.97 61.65,105.85 ; 62.94,102.69 65.44,100.2 v1(71.65,100.2)
+5V: length 69.4
  TOP w0.8: 60.3,104.43 60.3,103.9 61.3,102.9 66.65,102.9 v1(78.03,91.53) ; SW16.1 SW9.1 90.75,63.95 C33.1
  BOTTOM w0.8: SW9.1 88.3,62 79.55,70.75 79.55,90 v1(78.03,91.53)
GND_SIGNAL: length 776.9
  TOP w0.305: 59.05,103.4 59.05,105.8
  TOP w0.4: R12.2 90.15,100.1 D9.1 ; 59.05,103.4 60.7,101.75 66.2,101.75 78.01,89.94 78.01,65.69 88.3,55.4 88.3,54.03 89.28,53.05 97.85,53.05 98.1,52.8 ; 57.76,106.97 57.88,106.97 59.05,105.8 ; 40.1,33.82 39.7,33.42 36.65,33.42 v1(36.33,33.74) ; C31.2 6.95,69 4.6,71.35 C26.2 4.6,73 v1(5.65,74.05) ; v1(8.8,82.24) 8.8,81.25 R32.1 9.69,80.64 9.69,82.39 10.65,83.35 17.91,83.35 18.78,82.48 v1(18.78,82.3) 19.85,83.38 25.92,83.38 27.76,81.54 R23.1 ; R27.1 7.5,60.4 7.15,60.4 6.45,59.7 v1(6.1,59.7) ; 46.52,31.47 46.52,32.02 43.73,34.81 v1(43.73,35.46) ; v1(51.08,37.29) 51.08,36.01 51.48,35.61 53.32,35.61
  TOP w0.5: C29.2 17.59,57.92 ; C23.2 24.7,63.35 20.9,63.35 19.89,62.34 U1.11
  TOP w0.6: 47.95,88.85 43.56,88.85 43.56,89.22 ; 47.95,88.85 48.37,89.27 C11.2 ; 47.95,88.85 52.82,88.85 ; R27.1 9,59 9,56.9 9.45,56.45 11.92,56.45 13.38,57.92 17.59,57.92 17.94,58.27 R6.1 18.92,58.7 19.05,58.7 19.89,59.54 U1.11 ; v1(10.6,86.11) 10.71,86.23 10.71,86.46 10.2,85.95 8.45,85.95 2.05,79.55 2.05,53.5 7.1,48.45 7.1,47.75 15.5,47.75 C3.2 ; 52.82,88.85 62.31,88.85 ; 52.82,88.85 53.17,89.2 C10.2 C14.2 ; 62.31,88.85 62.8,89.34 62.8,90.48 R11.1 ; 62.31,88.85 69.47,88.85 70.07,89.45 70.07,90.43 C15.2 ; R11.1 65.18,90.49 C16.2 ; R11.1 62.78,90.48 C8.2 ; 43.56,89.22 C19.2 ; 43.56,89.22 43.21,88.87 39.22,88.87 38.78,89.31 38.78,90.47 C18.2 38.75,91.75 v1(38.45,92.05) ; v1(18.4,56.7) 18.05,56.35 17.59,56.35 ; 98.1,46.8 98.1,52.8 TP27.1 ; v1(18.78,82.3) 20.1,80.98 20.1,80.65 C22.2 17.3,77.85 17.3,77.2 21.5,73 v1(21.3,73) ; C21.2 29.76,61.45 30.05,61.45 31.34,62.74 31.34,66.41 30.9,66.85 C25.2
  TOP w0.8: v1(14.1,19.75) 14.89,18.96 14.22,18.29 TP21.1 ; v1(82.55,84.65) R41.2 C36.2 ; C23.2 25.84,61.07 26.2,61.43 C21.2 ; J5.5 94.05,73.72 C34.2 94.05,66.7 93.1,65.75 v1(86.8,65.75) 86.8,63.75 C33.2 C32.2 ; 26.1,19.5 26.23,19.37 TP21.2 ; C17.2 75.31,54.25 v1(76.65,55.59) ; C35.2 82.55,93.15 R40.2 82.5,94.03 ; v1(82.55,74.45) R42.2 82.55,70.05 ; 82.5,94.03 82.5,95.5 C13.1 ; 82.5,94.03 83.65,95.18 v1(83.65,95.2) ; C4.2 22.48,47.75 24.05,47.75 27.62,51.32 27.62,55.78 ; C13.1 81.62,96.38 C12.2 ; C13.1 82.4,95.7 84.1,97.4 88.1,97.4 88.85,98.15 D9.1 88.59,99.06 J4.1
  TOP w1: 25.84,61.07 25.84,57.56 27.62,55.78
  BOTTOM w0.4: v1(8.8,82.24) 8.8,82 2.1,75.3 2.1,53.61 21.31,34.4 35.07,34.4 35.73,33.74 v1(36.33,33.74) ; v1(51.08,37.29) 50.55,37.82 25.01,37.82 19.62,43.21 19.62,49.76 16.62,52.76 13.57,52.76 11.05,55.28 11.05,77.25 15.98,82.18 15.98,82.2 16.26,82.48 18.6,82.48 v1(18.78,82.3) ; v1(5.65,74.05) 5.55,73.95 5.55,63.05 6.4,62.2 6.4,60 v1(6.1,59.7) 6.52,59.28 6.52,52.53 22.98,36.07 43.12,36.07 v1(43.73,35.46)
  BOTTOM w0.5: v1(76.65,55.59) 76.65,53.43 77.99,52.09 97.39,52.09 TP27.1
  BOTTOM w0.6: v1(18.4,56.7) 18.4,68.4 21.3,71.3 21.3,72.8 21.5,73 v1(21.3,73) ; J2.2 28.44,108.35 22.3,108.35 17.55,103.6 17.55,89.8 13.86,86.11 v1(10.6,86.11)
  BOTTOM w0.8: C21.2 29.86,61.43 31.57,63.14 31.57,73.57 34.48,76.48 38.13,76.48 U2.1 38.12,76.5 TP22.1 38.12,90.63 38.45,90.96 v1(38.45,92.05) ; TP27.1 98.4,53.7 96.5,53.7 94.77,55.43 94.77,63.63 92.65,65.75 v1(86.8,65.75) 86.8,68.8 82.55,73.05 v1(82.55,74.45) v1(82.55,84.65) 82.55,94.1 v1(83.65,95.2)
  vias: v1(2.1,19.75) v1(2.36,47.07) v1(4.86,47.07) v1(5.1,19.75) v1(7.21,47.11) v1(8.1,19.75) v1(11.1,19.75) v1(15.57,38.3) v1(17.14,25.04) v1(17.14,22.55) v1(17.1,19.75) v1(20.14,25.04) v1(20.14,22.55) v1(20.1,19.75) v1(23.14,25.04) v1(23.14,22.55) v1(23.1,19.75) v1(26.14,25.04) v1(26.14,22.55) v1(37.65,30.21) v1(38.6,26.39) v1(39.65,30.21) v1(39.65,28.21) v1(39.7,24.86) v1(40.6,26.39) v1(41.65,30.21) v1(41.65,28.21) v1(41.7,24.86) v1(42.6,26.39) v1(43.65,30.21) v1(43.65,28.21) v1(43.7,24.86) v1(44.75,26.29) v1(45.8,28.11) v1(45.85,24.76) v1(46.75,26.29) v1(47.8,28.11) v1(47.85,24.76) v1(73.3,12) v1(73.3,10) v1(73.3,8) v1(75.2,12) v1(77.55,12)
+BUS: length 34.5
  TOP w0.305: 84.28,9.52 J1.1
  TOP w0.4: R1.1 97.26,35.21 97.26,31.12 84.28,18.14 84.28,9.52
  TOP w0.6: 69.6,56.2 C17.1
  BOTTOM w3: 76.98,38.91 C1.1
  vias: v1(67.5,54.4) v1(67.55,52.75) v1(67.53,51.27) v1(67.65,55.95) v1(69.45,56.25) v1(69.53,50.8) v1(69.55,52.3) v1(85.43,11.72) v1(86.95,11.75) v1(86.95,9.75) v1(86.95,7.75)
BUS_VOLTAGE: length 91.7
  TOP w0.254: 46.33,104.12 46.33,105.7
  TOP w0.4: R3.2 92.6,50.7 D1.1 ; R3.2 90.98,50.1 87.6,53.48 87.6,54.9 77.33,65.17 77.33,89.67 65.95,101.05 59.05,101.05 57.1,103 47.24,103 46.33,103.91 46.33,104.12 ; R3.2 94.55,50.1 C2.1 ; 45.06,106.97 45.06,106.97 46.33,105.7
CURRENT_A: length 29.9
  TOP w0.4: SW1.2 34.04,94.23 v1(47.6,94.23)
  BOTTOM w0.4: v1(47.6,94.23) J2.15
CURRENT_A_AMP: length 26.4
  TOP w0.6: TP24.1 28.34,72.55 R22.1 C25.1
  BOTTOM w0.4: TP24.1 28.29,83.28 31.11,86.1 31.11,91 SW1.1
CURRENT_B: length 37.5
  TOP w0.4: SW2.2 25.81,89.94 26.05,89.94 27.33,91.22 27.33,93.26 29.28,95.21 49.97,95.21 50.14,95.04 v1(50.14,94.92)
  BOTTOM w0.4: v1(50.14,94.92) J2.17
CURRENT_B_AMP: length 47.9
  TOP w0.4: D10.1 10.95,55.05 R43.1 13.05,55.1 13.07,55.12 C29.1 15.32,56.15 v1(15.32,56.37)
  BOTTOM w0.4: v1(15.32,56.37) 15.15,56.54 15.15,68.05 TP25.1 19.5,75.7 23.44,79.64 23.44,89.93 24.65,91.14 24.65,91.32 SW2.1
CURRENT_C: length 43.5
  TOP w0.4: v1(52.2,95.9) 24.82,95.9 24.08,95.16 24.08,91.61 22.36,89.89 SW3.2
  BOTTOM w0.4: v1(52.2,95.9) 52.29,95.99 52.29,104.04 52.68,104.43
CURRENT_C_AMP: length 32
  TOP w0.4: C31.1 R31.1 13.25,72.3 TP26.1
  BOTTOM w0.4: TP26.1 14.6,72.45 22.39,80.24 22.39,83.6 20.59,85.4 20.59,91.06 SW3.1
E1: length 178.5
  TOP w0.4: v1(21.27,82.27) 21.4,82.4 24.15,82.4 25.16,81.39 R21.1 ; 52.33,38.42 51.42,39.33 v1(51.08,39.33) ; D5.1 17.09,87.3 19.45,84.94 27.29,84.94 SW1.3 ; 52.18,40.87 v1(51.23,40.87)
  BOTTOM w0.4: v1(51.23,40.87) 50.4,41.7 28.77,41.7 24.85,45.62 24.85,76.45 26.77,78.37 26.77,84.42 SW1.3 ; v1(21.27,82.27) 19.85,80.85 16.35,80.85 11.75,76.25 11.75,55.71 13.89,53.57 16.9,53.57 20.37,50.1 20.37,43.51 25.3,38.58 50.33,38.58 v1(51.08,39.33)
E2: length 156.2
  TOP w0.4: SW2.3 24.29,85.88 20.82,85.88 17.1,89.6 D4.1 ; v1(6.5,63.9) 6.5,63.8 7.2,63.1 R26.1 ; v1(43.86,40.73) 43.86,40.25 ; v1(43.93,36.83) 46.93,36.83
  TOP w0.5: 43.86,40.25 44.78,39.33 45.55,39.33 R17.1 47.35,37.24 46.93,36.83
  BOTTOM w0.4: v1(43.93,36.83) 43.73,37.03 23.36,37.03 7.43,52.96 7.43,62.87 6.5,63.8 v1(6.5,63.9) ; v1(43.86,40.73) 28.53,40.73 24.1,45.16 24.1,77.35 25.77,79.02 SW2.3
  BOTTOM w2: 48.13,61.82 48.13,54.71 47.28,53.86
  BOTTOM w2.4: 47.28,53.86 TP11.1
  vias: v1(45.94,55.3) v1(45.89,44.45) v1(47.03,56.23) v1(47.39,44.45) v1(48.18,58.59) v1(48.18,57.09) v1(48.89,44.45)
E3: length 155.8
  TOP w0.4: 38.96,38.42 36.16,35.62 36.16,35.22 v1(35.95,35.01) ; R30.1 12.1,81.3 11.3,82.1 v1(11.05,82.1) ; v1(24.4,88.6) 24.4,88.28 23.47,87.35 SW3.3 17.46,91.85 D3.1
  TOP w0.5: 38.53,37.99 39.05,37.99 R16.1 39.39,39.65 v1(36.05,39.65)
  BOTTOM w0.4: v1(35.95,35.01) 35.67,35.29 21.38,35.29 2.68,53.99 2.68,73.93 10.85,82.1 v1(11.05,82.1) ; v1(24.4,88.6) 24.4,79 23.48,78.08 23.48,44.31 28.15,39.65 v1(36.05,39.65)
EM_STOP: length 36.8
  TOP w0.6: SW4.2 36.25,87.3 R10.2 38.75,87.2 C18.1 38.75,85.2 39.48,84.48 TP4.1
  BOTTOM w0.4: J2.1 29.9,104.35 29.9,103 35.02,97.88 35.02,88.86 SW4.2
  BOTTOM w0.5: 39.9,76.5 39.9,76.48 U2.2
  BOTTOM w0.6: TP4.1 39.89,84.07 39.94,84.02 U2.2
M_PHASE_A: length 38.9
  TOP w0.6: C35.1 85.15,90.65 84.2,91.6 84.2,94.19 SW13.2
  TOP w0.8: C35.1 R34.2 88.3,88.15 R37.2 88.3,90.44 SW10.2
  BOTTOM w0.6: J2.31 67.85,104.36 67.85,103.75 68.98,102.62 82.78,102.62 85.86,99.54 SW13.2
M_PHASE_B: length 50.7
  TOP w0.6: SW14.2 84.28,83.87 84.28,80.77 84.7,80.35 C36.1
  TOP w0.8: C36.1 85.85,77.9 R35.2 R38.2 88.3,80.24 SW11.2
  BOTTOM w0.6: J2.33 71.09,103.8 83.05,103.8 90.05,96.8 90.05,94.75 85.91,90.61 SW14.2
M_PHASE_C: length 64.2
  TOP w0.6: C37.1 85,70.05 84.35,70.7 84.35,74.8 84.77,75.22 85.83,75.22 SW15.2 ; v1(84.85,68.35) 85.65,67.55 R36.2 ; J2.34 70.49,107 75.34,107 v1(80.95,101.39)
  TOP w0.8: C37.1 R36.2 88.3,67.55 R39.2 88.3,69.89 SW12.2
  BOTTOM w0.6: v1(84.85,68.35) 80.95,72.25 v1(80.95,101.39)
NANO OP+: length 103.4
  TOP w0.4: v1(19.01,96.79) 20.02,97.8 v1(49.05,97.8) ; U1.10 18.62,62.83 17.34,64.11 12.01,64.11 11,63.1 R26.2 R25.1 9.75,64.5 v1(9.3,64.5)
  BOTTOM w0.4: v1(49.05,97.8) 49.05,86.37 TP6.1 ; v1(19.01,96.79) 18.87,96.65 18.87,88.52 9.3,78.95 v1(9.3,64.5)
  BOTTOM w0.5: U2.6 47.2,76.48
  BOTTOM w0.6: 47.2,76.48 47.2,76.45 ; TP6.1 47.16,84.03 47.14,84 U2.6
NANO OP-: length 105.8
  TOP w0.4: 13.4,60.77 11.07,60.77 10.85,60.55 R27.2 R29.1 10.25,58.35 10.25,58.95 v1(10.1,59.1) ; 13.4,60.77 C27.2 ; 13.4,60.77 13.93,60.25 16.8,60.25 17.35,60.8 17.35,61.61 ; v1(19.92,95.62) 21.16,96.86 v1(51.11,96.86)
  BOTTOM w0.4: v1(51.11,96.86) 51.11,91.26 50.75,90.9 50.75,85.76 50.74,85.75 TP8.1 ; v1(19.92,95.62) 19.74,95.44 19.74,87.69 10.25,78.2 10.25,59.25 v1(10.1,59.1)
  BOTTOM w0.5: U2.8 50.75,76.48
  BOTTOM w0.6: 50.75,76.48 50.75,75.9 ; U2.8 TP8.1
NANO OPOUT: length 83.5
  TOP w0.4: 37.61,74.6 35.52,76.69 35.52,82.72 34.09,84.15 8.1,84.15 3.05,79.1 3.05,57.87 SW17.3 5.05,55.87 TP7.1
  TOP w0.5: 37.61,74.6 48.48,74.6 48.94,75.06 U2.7
Net_29: length 0
  TOP w0.8: 60.64,61.94 60.62,61.92
Net_30: length 1.9
  TOP w0.8: 43.14,60.09 43.14,62.01
NTC: length 40.5
  TOP w0.4: v1(57.53,95.07) 55.69,93.23 34.71,93.23 33.46,91.98 SW4.1
  BOTTOM w0.4: 60.3,106.97 59.03,105.7 59.03,97.11 57.53,95.61 v1(57.53,95.07)
PHASE_A: length 63.2
  TOP w0.8: 59.29,64.86 59.5,64.86 58.4,65.96 58.4,67.46 D8.1 ; 59.29,64.86 59.26,64.83 C5.2 ; 59.29,64.86 59.4,64.97 59.87,64.97 60.67,64.17 TP18.1
  BOTTOM w0.8: 60.64,56.64 60.67,56.67 TP18.1
  BOTTOM w2: 60.64,56.64 60.64,53.5
  BOTTOM w4: J3.1 58.16,11.26 63.05,16.15 63.05,51.09 60.64,53.5
PHASE_B: length 60.8
  TOP w0.8: D7.1 50.44,67.32 50.44,65.26 50.72,64.98 C6.2 50.64,64.72 U2.22
  BOTTOM w1: TP10.1 50.61,52.07 51.37,51.31
  BOTTOM w4: J3.2 50.54,15.14 56.24,20.84 56.24,44.09 51.37,48.96 51.37,51.31
PHASE_C: length 48.9
  TOP w0.8: TP1.1 U2.25 40.65,61.95 40.65,63.97 C7.2 41.91,65.23 D6.1
  TOP w4: J3.3 42.92,11.83 31.75,23 31.75,45.34
  vias: v1(30.45,47.11) v1(30.41,45.62) v1(31.81,47.08) v1(31.82,45.63) v1(33.12,47.06) v1(33.15,45.58)
PWM-A-H: length 42.3
  TOP w0.4: J2.3 32.36,103.54 36.47,99.43 60.02,99.43 67.5,91.95 67.5,90.59 R19.1
PWM-A-L: length 44.7
  TOP w0.4: R13.1 72.4,90.5 72.4,92.05 64.29,100.16 38.29,100.16 34.9,103.55 J2.5
PWM-B-H: length 29.8
  TOP w0.4: R8.1 50.78,90.51 50.78,91.45 51.58,92.25 v1(52.07,92.25) ; J2.7 37.44,103.51 39.75,101.2 v1(53.29,101.2)
  BOTTOM w0.4: v1(53.29,101.2) 53.29,95.3 52.07,94.08 v1(52.07,92.25)
PWM-B-L: length 29.1
  TOP w0.4: J2.9 39.98,103.67 41.5,102.15 54.22,102.15 54.35,102.02 v1(54.66,102.02) ; R14.1 57.98,91.44 v1(56.86,92.56)
  BOTTOM w0.4: v1(54.66,102.02) 54.61,101.97 54.61,96.07 56.86,93.82 v1(56.86,92.56)
PWM-C-H: length 15.4
  TOP w0.4: R7.1 41.16,91.07 v1(40.08,92.15)
  BOTTOM w0.4: v1(40.08,92.15) 42.52,94.59 J2.11
PWM-C-L: length 14.5
  TOP w0.4: R9.1 45.96,91.02 v1(44.82,92.16)
  BOTTOM w0.4: 45.06,104.43 44.82,104.19 v1(44.82,92.16)
N6680355: length 3.7
  TOP w0.6: R1.2 98.4,39.65 R2.1
N6680429: length 7.1
  TOP w0.6: R3.1 92,46.8 R4.1 95.1,46.5 R2.2
N7418873: length 13.2
  TOP w0.6: 43.56,87.2 43.55,87.19 43.55,85.89 43.53,85.87 TP2.1 ; 43.56,87.2 R7.2 ; 43.56,87.2 C19.1
  BOTTOM w0.5: U2.4 43.54,76.48
  BOTTOM w0.6: 43.55,76.45 43.54,76.46 43.54,76.48 ; U2.4 43.54,83.1 43.53,83.11 TP2.1
N7419173: length 15.1
  TOP w0.6: 48.36,87.2 47.24,86.07 46.96,86.07 46.9,86.01 46.17,86.01 45.41,85.25 TP5.1 ; 48.36,87.2 C11.1 ; 48.36,87.2 R9.2
  BOTTOM w0.5: U2.5 45.32,76.48
  BOTTOM w0.6: 45.4,76.4 45.32,76.48 45.32,76.48 ; TP5.1 45.41,79.45 45.34,79.38 U2.5
N7419575: length 16.8
  TOP w0.6: R13.2 72.4,87.2 C15.1 70.02,87.18 70.02,86.68 67.78,84.44 TP20.1
  BOTTOM w0.6: TP20.1 65.1,84.03 65.14,83.99 U2.16
N7419579: length 15.3
  TOP w0.6: R19.2 65.19,87.2 C16.1 65.19,87.03 62.64,84.48 TP23.1
  BOTTOM w0.6: TP23.1 61.53,83.1 61.54,83.09 U2.14
N7419959: length 13.4
  TOP w0.6: 55.58,87.2 56.14,86.63 TP14.1 ; 55.58,87.2 R14.2 ; 55.58,87.2 C14.1
  BOTTOM w0.6: U2.11 56.14,79.44 56.14,79.45 TP14.1
N7419967: length 14.3
  TOP w0.6: TP12.1 54.24,84.48 53.31,85.41 53.31,87.06 C10.1 53.17,87.2 R8.2
  BOTTOM w0.5: U2.10 54.35,76.48
  BOTTOM w0.6: 54.35,76.48 54.35,75.9 ; U2.10 54.34,83.09 54.33,83.1 TP12.1
N8602926: length 14.6
  TOP w0.4: 22.6,77.2 23.69,77.2 23.7,77.21 25.09,77.21 ; R21.2 25.09,77.21 ; 25.09,77.21 23.6,75.72 23.6,71.8 21.36,69.56 C24.1 21.18,66.93 U1.3
N8603142: length 17.2
  TOP w0.4: U1.2 22.43,67.93 24.06,69.56 C24.2 24.48,73.93 R23.2 30.34,79.79 30.34,80.53 R24.1
N8608659: length 17.2
  TOP w0.4: 27.15,67.25 24.04,67.25 U1.1 ; 27.15,67.25 27.55,66.85 R22.2 ; 27.15,67.25 26.05,68.35 26.05,72.94 R24.2 30.3,77.29
N8611164: length 14.7
  TOP w0.7: C3.1 16.93,50.43 21.14,54.64 R5.1 21.14,56.35 21.14,56.36 21.14,56.38 21.79,57.03 R6.2 21.79,59.5 21.16,60.14 U1.12
N8745560: length 9.2
  TOP w0.4: R15.2 10.84,88.19 10.89,88.24 13.09,88.24 D5.2 D4.2 D3.2
N8758281: length 6.2
  TOP w0.4: SW17.2 5.76,57.7 6.41,57.7 6.46,57.75 R29.2 7.55,55.15 R43.2
N8759020: length 22.2
  TOP w0.4: 7,77.2 9.55,74.65 13.75,74.65 15.2,73.2 15.2,71.75 14.05,70.6 14.05,69 ; 14.05,69 R31.2 ; 14.05,69 14.05,68.35 15.49,66.91 U1.7
N8759128: length 14.6
  TOP w0.4: U1.5 18.62,69.47 C30.1 16.9,71.37 16.9,73.72 14.65,75.97 14.65,77.15 14.7,77.2 12.1,77.2
N8759136: length 20.5
  TOP w0.4: R33.1 9.55,77.95 9.55,76.85 10.9,75.5 14.15,75.5 16.05,73.6 16.05,70.2 C30.2 15.79,69.56 17.35,68 17.35,66.91
N8769015: length 21.7
  TOP w0.8: SW16.2 97.05,59.36 97.66,59.36 98.95,60.65 98.95,70.4 C34.1 97.5,72.15 97.5,76.75 96.39,77.86 J5.4
N8769177: length 39
  TOP w0.8: 80.75,77.9 R35.1 ; 80.75,77.9 80.75,86.35 R34.1 ; 80.75,77.9 80.75,68.65 81.85,67.55 R36.1 82.55,65.55 v1(82.53,65.53)
  BOTTOM w0.8: SW9.2 92.61,59.55 88.5,59.55 v1(82.53,65.53)
N8769259: length 11.6
  TOP w0.8: R37.1 91.6,90.4 SW10.1
  BOTTOM w0.8: J5.1 92.97,85.48 91.2,87.25 SW10.1
N8769267: length 8.3
  TOP w0.8: SW11.1 91.6,80.2 R38.1
  BOTTOM w0.8: SW11.1 93.54,82.94 J5.2
N8783110: length 14.9
  TOP w0.8: SW12.1 91.6,69.85 91.6,67.55
  BOTTOM w0.8: SW12.1 91.2,75.95 J5.3
N8796833:
  vias: v1(58.67,60.5)
N8856248: length 10.8
  TOP w0.5: U2.24 43.15,61.94
  TOP w0.8: D6.2 45.71,65.73 C7.1 44.83,63.87 43.15,62.19 TP9.1
N8867925: length 79.6
  TOP w0.4: v1(59.37,95.54) 56.15,98.76 18.65,98.76 11.43,91.54 10.89,91.54 10.84,91.49 R15.1 ; 62.79,87.19 62.35,86.74 v1(61.67,86.74)
  TOP w0.6: 62.79,87.19 60.39,87.19 C8.1 59.73,86.52 59.73,85.55 58.66,84.48 TP15.1
  BOTTOM w0.4: v1(59.37,95.54) 59.37,94.96 59.31,94.9 59.31,89.1 v1(61.67,86.74)
  BOTTOM w0.6: U2.12 57.94,83.09 57.92,83.1 TP15.1
N8869100: length 10.3
  TOP w0.5: U2.21 55.59,61.94
  TOP w0.8: TP13.1 55.59,63.23 C6.1 54.22,65 D7.2
N8869824: length 10.6
  TOP w0.5: 65.64,61.94 U2.17
  TOP w0.8: D8.2 62.11,65.41 62.56,64.96 C5.1 63.06,64.81 65.64,62.23 65.64,61.94 66.42,61.94 TP19.1
N8877212: length 95.4
  TOP w0.8: D9.2 82.5,98.8 C13.2 ; J4.2 83.51,104.03 83.5,104.02 83.5,103.85 82.4,102.75 C13.2 ; C13.2 77.17,98.9 C12.1
  BOTTOM w0.5: J4.2 94.26,95.2 D2.1 ; U2.3 41.7,76.48 ; 52.5,76.25 52.5,76.48 U2.9 ; 59.75,76.48 U2.13
  BOTTOM w0.6: U2.13 59.74,79.45 59.74,79.45 TP3.1 ; 51.55,74.68 52.5,75.63 52.5,76.25 ; 59.75,76.48 59.75,74.97 59.46,74.68
  BOTTOM w0.8: C12.1 75.46,98.92 71.37,94.83 71.37,79.27 66.78,74.68 42.17,74.68 41.7,75.15 41.7,76.55
N8885403: length 12.2
  TOP w0.4: SW17.1 6.05,61.45 6.4,61.8 11.9,61.8 12.45,62.35 15.34,62.35 U1.8
N8906266: length 4.3
  TOP w0.6: R42.1 86.9,72.55 88.4,74.05 SW15.1
N8906381: length 4.5
  TOP w0.6: SW14.1 88.5,85.45 88.5,84.3 87,82.8 R41.1
N8906601: length 4.4
  TOP w0.6: SW13.1 88.4,94.6 87,93.2 R40.1
N88772240: length 5
  TOP w0.5: D2.2 96.8,99.8 96.5,100.1

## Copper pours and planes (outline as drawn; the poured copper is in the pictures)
GND_SIGNAL on TOP (solid shape): 27.45,62.2 30.2,62.2 30.5,61.9 30.5,61.25 30.05,60.8 27.05,60.8 26.45,60.2 26.45,57.9 29.1,55.25 29.1,50.11 27.25,48.26 27.25,17.91 26.49,17.15 1.49,17.15 0.86,17.78 0.86,47.62 1.74,48.5 23.58,48.5 26.8,51.72 26.8,55.9 24.85,57.85 24.85,62.7 25.15,63 26.65,63
GND_SIGNAL on TOP (solid shape): 89.02,44.88 89.02,30.31 78.25,19.54 78.25,7.15 77.75,6.65 73.05,6.65 72.5,7.2 72.5,16.1 70.1,18.5 43.5,18.5 37.05,24.95 37.05,35.28 37.83,36.06 41.61,36.06 43.63,34.04 51.03,34.04 53.05,36.07 57.98,36.08 60.12,33.87 79.53,33.91 82.2,36.58 82.2,42.65 73.1,51.75 73.1,56.2 77.7,56.2
GND_SIGNAL on BOTTOM (solid shape): 78.25,12.35 78.25,7.1 77.8,6.65 73.05,6.65 72.5,7.2 72.5,12.35 73.05,12.9 77.7,12.9
GND_SIGNAL on BOTTOM (solid shape): 78.27,12.34 78.27,7.09 77.82,6.64 73.07,6.64 72.52,7.19 72.52,12.34 73.07,12.89 77.72,12.89
GND_SIGNAL on BOTTOM (solid shape): 21.65,33.25 31.35,33.25 33.58,31.02 36.13,31.02 39.08,33.97 48.55,33.97 49.93,32.59 49.93,24.88 42.25,17.2 1.49,17.2 0.86,17.83 0.86,47.62 1.75,48.51 6.39,48.51
GND_SIGNAL on BOTTOM (solid shape): 91.25,110.79 91.25,104.9 90.65,104.3 87.55,104.3 87.1,104.75 87.1,108.6 86,109.7 81.4,109.7 80.25,108.55 80.25,105.8 79.2,104.75 72.95,104.75 72.45,105.25 72.45,107.9 72.1,108.25 69.6,108.25 69.15,107.8 69.15,106.15 68.9,105.9 65.05,105.9 64.5,106.45 64.5,108 64.1,108.4 59.3,108.4 58.7,107.8 58.7,106.55 58.05,105.9 46.9,105.9 46.35,106.45 46.35,108.05 46.1,108.3 44.15,108.3 43.8,107.95 43.8,106.3 43.4,105.9 26.42,105.9 17.91,97.6 17.91,89.62 13.36,85.2 4.3,85.2 4.3,98.45 17.65,111.8 90.24,111.8
+BUS on TOP (solid shape): 70.6,56.45 70.6,50.01 67.91,50.01 66.9,51.02 66.9,56.4 67.3,56.8 70.25,56.8
+BUS on TOP (solid shape): 87.62,12.29 87.62,7.04 87.17,6.59 82.42,6.59 81.87,7.14 81.87,12.29 82.42,12.84 87.07,12.84
+BUS on TOP (solid shape): 64.2,62.2 64.2,58.05 65.45,56.8 70.25,56.8 70.6,56.45 70.6,50.36 70.21,49.97 67.98,49.97 62.2,55.75 62.2,62.4 62.5,62.7 63.7,62.7
+BUS on BOTTOM (solid shape): 64.2,62.2 64.2,58.05 65.44,56.81 70.24,56.81 72.09,55.03 72.11,47.94 87.61,32.4 87.63,12.28 87.63,7.05 87.17,6.59 82.42,6.59 81.87,7.14 81.94,30.4 66.62,45.71 66.65,51.28 62.2,55.75 62.2,62.4 62.5,62.7 63.7,62.7
E1 on TOP (solid shape): 54.7,47.33 57.27,44.76 57.27,36.56 51.97,36.56 51.97,43.41 49.89,45.49 49.89,48.72 54.7,48.72
E2 on TOP (solid shape): 49.17,62.53 49.18,56.63 49.64,56.18 49.64,51.97 49.46,51.79 49.46,44.88 50,44.34 50,34.74 44.7,34.74 44.7,44.38 45.44,45.13 45.44,51.77 45.29,51.92 45.29,55.84 46.72,57.3 46.7,62.55 47.1,62.95 48.75,62.95
E2 on BOTTOM (solid shape): 49.17,62.53 49.17,54.16 48.47,53.46 48.47,46.59 50,45.06 50,43.81 49.94,43.75 44.8,43.75 44.7,43.85 44.7,45.4 46.04,46.74 46.04,51.62 45.29,52.37 45.29,55.82 46.73,57.26 46.73,62.57 47.11,62.95 48.75,62.95
E3 on TOP (solid shape): 45,45.73 42.69,43.42 42.69,36.67 37.39,36.67 37.39,44.83 40.11,47.55 40.11,48.73 45,48.73
PHASE_A on TOP (solid shape): 60.26,65.39 60.26,64.25 61.67,62.81 61.67,56.7 61.41,56.44 59.86,56.44 59.62,56.68 59.62,63.04 58.43,64.23 58.43,65.65 59.99,65.65
PHASE_A on BOTTOM (solid shape): 61.67,62.61 61.67,55.19 65.03,51.83 65.03,49.75 64.78,49.5 61.83,49.5 58.72,52.61 58.72,54.52 58.76,54.52 59.62,55.38 59.62,62.66 59.93,62.97 61.31,62.97
PHASE_B on TOP (solid shape): 51.96,62.6 51.96,56.81 51.63,56.48 50,56.48 49.65,56.83 49.65,62.58 50.01,62.94 51.62,62.94
PHASE_B on BOTTOM (solid shape): 51.96,62.6 51.96,56.16 53.36,54.76 53.36,51.38 49.65,51.38 49.4,51.63 49.66,52.28 49.65,62.59 49.99,62.94 51.62,62.94
PHASE_C on TOP (solid shape): 33.75,47.82 33.75,45.11 33.43,44.79 30.08,44.79 29.8,45.07 29.8,47.65 30.49,48.34 33.23,48.34
PHASE_C on TOP (solid shape): 41.62,62.58 41.62,56.83 41.26,56.47 40.01,56.47 39.67,56.81 39.67,62.59 39.92,62.84 41.36,62.84
PHASE_C on BOTTOM (solid shape): 41.62,62.58 41.62,54.85 40.8,54.03 35.46,54.05 33.77,52.37 33.73,45.08 33.43,44.78 30.08,44.78 29.77,45.13 29.78,51.19 29.78,53.78 33.17,57.21 39,57.21 39.67,57.88 39.67,62.59 39.92,62.84 41.36,62.84
N8796833 on TOP (solid shape): 59.27,62.46 59.27,50.86 57.54,49.13 49.9,49.13 49.9,51.64 52.78,54.52 55.69,54.52 57.03,55.86 57.03,62.61 57.41,62.99 58.74,62.99
N8796833 on BOTTOM (solid shape): 59.27,62.46 59.27,55.84 58.78,55.35 57.33,55.35 57.03,55.65 57.03,62.61 57.41,62.99 58.74,62.99
N8857786 on TOP (solid shape): 39.15,62.44 39.15,59.68 38.64,59.17 38.64,55.8 39.66,54.78 41.9,54.78 45,51.68 45,49.14 36.11,49.14 34.39,50.86 34.39,62.07 35.52,63.2 38.39,63.2

Small or netless copper shapes (teardrops, artwork), in the pictures only: 4 on TOP, 5 on BOTTOM

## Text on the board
Ref Des/Assembly Top: STEVAL-IPMNntmp | G | 5 | 0 | N | Q | 1 | M | 7 | 2 | 8 | 3 | 9 | 4 | t | m | p | 6
Ref Des/Silkscreen Top: ASSEMBLY | ON THE | BOTTOM | U2 | GND | NW | TSO | OUTW | VCCW | VBW | HINW | LINW | OP+ | NV | OPOUT | OP- | OUTV | VCCV | HINV | VBV | LINV | CIN | NU | VCCU | OUTU | HINU | P | TSO1 | VBU | LINU | STEVAL-IPMntmp | G | 5 | 0 | N | NOT | 6 | Q | 1 | M | FCC | FOR | 7 | 2 | APPROVED | EVALUATION | 8 | 3 | 9 | 4 | ONLY | RESALE | 400 | Vdc | max | ON | connector | Hall | 3V3 | 5V | CONTROL CONNECTOR | 20V | Vcc | t | m | p | W | V | U | +
XSECTION_CHART: *  SURFACE - AIR 0 MM | L1: TOP CONDUCTOR - COPPER 0.07 MM | *  DIELECTRIC - FR-4 1.46 MM | L2: BOTTOM CONDUCTOR - COPPER 0.07 MM | DESIGN CROSS SECTION CHART | ___________________________ | TOTAL THICKNESS 1.6 MM | 1-2 | FIGURE | SIZE | 0.6096 | 0.7112 | 0.813 | 0.9906 | 1.1989 | 1.3 | 1.905 | 3.2 | 7.0 | DRILL CHART: TOP to BOTTOM | ALL UNITS ARE IN MILLIMETERS | PLATED | NON-PLATED | QTY | 128 | 8 | 2 | 26 | 1 | 32 | 90 | 7 | 4
